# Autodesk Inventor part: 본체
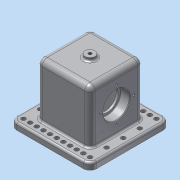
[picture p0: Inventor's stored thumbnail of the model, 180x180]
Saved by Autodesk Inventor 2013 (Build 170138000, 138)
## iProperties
Created: 2018-11
Part Number: 본체
Material: 알루미늄 6061
Document SubType Name: Modeling
Designer: dgall
Density: 1 g/cm^3
Mass: 376.663 g
Surface Area: 777.082 cm^2
Volume: 376.663 cm^3
Author: dgall
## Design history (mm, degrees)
sketch "스케치1"
  geometry: L1 (-40, 40)-(40, 40); L2 (40, 40)-(40, -40); L3 (40, -40)-(-40, -40); L4 (-40, -40)-(-40, 40); 3 further points
  constraints: 8 end point, 2 midpoint, 2 parallel, 1 horizontal, 1 horizontal alignment, 1 perpendicular, 1 vertical alignment
  dimensions: "d0" = 80 distance of L2.end L3.end; "d1" = 80 distance of L1.end L2.end
extrude "돌출1" new body sketch "스케치1" stored distance "d2" = 90; taper "d3" = 0 deg
sketch "스케치3"
  geometry: L1 (23, 35)-(-23, 35); L2 (-23, 35)-(-23, -45); L3 (-23, -45)-(23, -45); L4 (23, -45)-(23, 35); L5 (40, -45)-(-40, -45) reference; 3 further points
  constraints: 8 end point, 3 midpoint, 2 parallel, 1 horizontal, 1 perpendicular, 1 vertical alignment
  dimensions: "d6" = 46 distance of L2.end L3.end; "d8" = 80 distance of L1.end L2.end
sketch "스케치4"
  geometry: L1 (90, 80)-(90, 0) reference; C1 r 20 at (42, 40); 1 further point
  constraints: 1 centre point, 1 horizontal alignment
  dimensions: "d11" = 40 diameter of C1; "d12" = 48 distance from line of L1 C1.centre
extrude "돌출3" cut sketch "스케치4" distance "d13" = 14; taper "d14" = 0 deg
hole "구멍1" diameter "d17" = 33; stored, may be unused: countersink angle "d21" = 90 deg, drill point angle "d23" = 118 deg; dims "d15" = 10, "d16" = 10, "d18" = 6, "d19" = 4, "d20" = 2, "d22" = 8
sketch "스케치5" dims "d24" = 52
  geometry: C1 r 20 at (42, 40) reference; C2 r 2 at (16, 40); 2 further points
  constraints: 2 horizontal alignment, 1 centre point, 1 coincident, 2 other
  dimensions: "d25" = 4 diameter of C2
hole "구멍2" sketch "스케치5" at (16, 40) diameter "d26" = 3.242; stored, may be unused: countersink angle "d30" = 90 deg, drill point angle "d32" = 118 deg; dims "d27" = 8, "d28" = 4, "d29" = 2, "d31" = 10
node "작업 평면1"
sketch "스케치6"
  geometry: L1 (-60, 60)-(60, 60); L2 (60, 60)-(60, -60); L3 (60, -60)-(-60, -60); L4 (-60, -60)-(-60, 60); C1 r 3.3 at (-50, -50); C2 r 3.3 at (50, -50); 3 further points
  constraints: 8 end point, 2 centre point, 2 midpoint, 2 parallel, 1 horizontal, 1 horizontal alignment, 1 perpendicular, 1 vertical alignment
  dimensions: "d37" = 120 distance of L2.end L3.end; "d38" = 120 distance of L1.end L2.end; "d39" = 6.6 diameter of C1; "d40" = 10 distance from line of L3 C1.centre; "d41" = 10 distance from line of L4 C1.centre; "d49" = 6.6 diameter of C2; "d50" = 10 distance from line of L3 C2.centre; "d51" = 10 distance from line of L2 C2.centre
extrude "돌출4" join sketch "스케치6" distance "d42" = 10; taper "d43" = 0 deg
extrude "돌출5" cut sketch "스케치6" stored distance "d44" = 10; taper "d45" = 0 deg
extrude "돌출6" cut sketch "스케치6" stored distance "d52" = 10; taper "d53" = 0 deg
extrude "돌출7" cut sketch "스케치3" stored distance "d63" = 60; taper "d64" = 0 deg
sketch "스케치7"
  geometry: C1 r 7.5 at (0, 0); 1 further point
  constraints: 1 centre point, 1 coincident
  dimensions: "d65" = 15 diameter of C1
extrude "돌출8" join sketch "스케치7" distance "d66" = 5; taper "d67" = 0 deg
fillet "모깎기1" dims "d68" = 8
fillet "모깎기2" dims "d69" = 8
hole "구멍3" diameter "d72" = 4.917; stored, may be unused: countersink angle "d76" = 90 deg, drill point angle "d78" = 118 deg; dims "d70" = 10, "d71" = 10, "d73" = 8, "d74" = 4, "d75" = 2, "d77" = 10
fillet "모깎기4" dims "d80" = 3
fillet "모깎기5" dims "d81" = 3
fillet "모깎기6" dims "d82" = 3
fillet "모깎기7" dims "d83" = 3
fillet "모깎기8" dims "d84" = 0.6
chamfer "모따기1" distance "d85" = 1; stored, may be unused: second distance "d86" = 2, angle "d87" = 45 deg
sketch "스케치8"
  geometry: L1 (-28, 82)-(92, 82) reference; 2 further points
  constraints: 1 vertical alignment, 1 other
  dimensions: "d88" = 48 distance from line of L1 point (32, 34)
feature "엠보싱1" sketch "스케치8" dims "d14" = 0, "d89" = 0.5, "d90" = 0
fillet "모깎기9" dims "d91" = 10
fillet "모깎기10" dims "d92" = 3
node "솔리드1"
pattern_circular "원형 패턴1" dims angle "d34" = 360 deg
mirror "대칭1"
pattern_linear "직사각형 패턴2" dims "d56" = 10
pattern_linear "직사각형 패턴3" dims "d59" = 25
pattern_linear "직사각형 패턴4" dims "d62" = 25
mirror "대칭2"
other parameters: "d36" = -45
